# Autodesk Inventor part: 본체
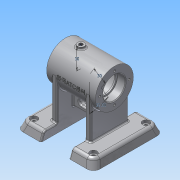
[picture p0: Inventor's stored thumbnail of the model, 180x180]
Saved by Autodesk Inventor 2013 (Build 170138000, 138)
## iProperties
Created: 2008-12
Part Number: 본체
Material: 알루미늄 6061
Document SubType Name: Modeling
Designer: Administrator
Density: 2.71 g/cm^3
Mass: 496.94 g
Surface Area: 538.478 cm^2
Volume: 183.373 cm^3
Author: Administrator
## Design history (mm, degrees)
sketch "스케치1"
  geometry: C1 r 27 at (0, 0); 1 further point
  constraints: 1 centre point, 1 coincident
  dimensions: "d0" = 54 diameter of C1
extrude "돌출1" new body sketch "스케치1" distance "d1" = 35; taper "d2" = 0 deg
sketch "스케치2"
  geometry: C1 r 27 at (0, 0) reference; C2 r 16 at (0, 0)
  constraints: 1 centre point, 1 coincident
  dimensions: "d3" = 32 diameter of C2
extrude "돌출2" cut sketch "스케치2" distance "d4" = 12; taper "d5" = 0 deg
sketch "스케치3"
  geometry: C1 r 16 at (0, 0) reference; C2 r 14 at (0, 0)
  constraints: 1 centre point, 1 coincident
  dimensions: "d6" = 28 diameter of C2
extrude "돌출3" cut sketch "스케치3" distance "d7" = 2; taper "d8" = 0 deg
sketch "스케치4"
  geometry: C1 r 14 at (0, 0) reference; C2 r 22 at (0, 0)
  constraints: 1 centre point, 1 coincident
  dimensions: "d9" = 44 diameter of C2
extrude "돌출4" cut sketch "스케치4" stored distance "d10" = 2; taper "d11" = 0 deg
chamfer "모따기1" distance "d12" = 1; stored, may be unused: second distance "d13" = 2, angle "d14" = 45 deg
fillet "모깎기1" dims "d15" = 0.3
sketch "스케치5"
  geometry: L1 (0, 0)-(0, 21); C1 r 17 at (0, 0) reference; 1 further point
  constraints: 2 end point, 1 coincident, 1 vertical
  dimensions: "d16" = 21 distance of L1.start L1.end
hole "구멍1" sketch "스케치5" at (0, 21) diameter "d17" = 3.242; stored, may be unused: countersink angle "d21" = 90 deg, drill point angle "d23" = 118 deg; dims "d18" = 8, "d19" = 4, "d20" = 2, "d22" = 10
node "작업 평면1"
node "작업 평면3"
sketch "스케치9"
  geometry: L1 (0, 0)-(-30, 0)
  constraints: 2 end point, 1 horizontal
  dimensions: "d44" = 30 distance of L1.start L1.end
node "작업 평면4"
sketch "스케치10"
  geometry: L1 (-22, -27)-(-22, 27) reference; L2 (48, -27)-(48, 27) reference; C1 r 5 at (0, 0); 4 further points
  constraints: 1 centre point, 1 coincident
  dimensions: "d45" = 10 diameter of C1
extrude "돌출6" join sketch "스케치10" stored distance "d46" = 2; taper "d47" = 0 deg
sketch "스케치11"
  geometry: C1 r 5 at (0, 0) reference; 2 further points
  constraints: 1 coincident
hole "구멍3" sketch "스케치11" at (0, 0) diameter "d48" = 5.188; stored, may be unused: countersink angle "d52" = 90 deg, drill point angle "d54" = 118 deg; dims "d49" = 99, "d50" = 4, "d51" = 2, "d53" = 10
fillet "모깎기4" dims "d55" = 2
node "작업 평면5"
sketch "스케치13"
  geometry: L1 (0, 0)-(9.92, 0); L2 (0, 0)-(25.441, 15.898)
  constraints: 4 end point, 1 horizontal
  dimensions: "d57" = 30 distance of L1.start L2.end; "d58" = 32 deg angle of L1 L2
node "작업 평면6"
sketch "스케치14"
  geometry: C1 r 6 at (0, 0); 1 further point
  constraints: 1 centre point, 1 coincident
  dimensions: "d59" = 12 diameter of C1
extrude "돌출7" join sketch "스케치14" stored distance "d60" = 2; taper "d61" = 0 deg
fillet "모깎기5" dims "d62" = 2
hole "구멍4" diameter "d65" = 5.188; stored, may be unused: countersink angle "d69" = 90 deg, drill point angle "d71" = 118 deg; dims "d63" = 10, "d64" = 10, "d66" = 99, "d67" = 4, "d68" = 2, "d70" = 10
node "작업 평면8"
  node "작업 평면7"
sketch "스케치16"
  geometry: L1 (-55, -50)-(55, -50); L2 (55, -50)-(55, 50); L3 (55, 50)-(-55, 50); L4 (-55, 50)-(-55, -50); L5 (-55, -50)-(55, 50); L6 (55, -50)-(-55, 50); 1 further point
  constraints: 12 end point, 2 midpoint, 2 parallel, 1 horizontal, 1 perpendicular
  dimensions: "d74" = 110 distance of L3.end L2.end; "d75" = 100 distance of L2.end L1.end
extrude "돌출8" join sketch "스케치16" distance "d76" = 12; taper "d77" = 0 deg
sketch "스케치17"
  geometry: L1 (0, 0)-(110, 0) reference; L2 (110, 0)-(110, 12) reference; L3 (0, 12)-(110, 12) reference; L4 (105.632, 12)-(110, 0); 1 further point
  constraints: 2 end point, 1 point on line
  dimensions: "d78" = 110 deg angle of L1 L4
extrude "돌출9" cut sketch "스케치17" stored distance "d79" = 12; taper "d80" = 0 deg
sketch "스케치18"
  geometry: L1 (0, 100)-(0, 0) reference; L2 (0, 0)-(12, 0) reference; L3 (12, 100)-(12, 0) reference; L4 (0, 0)-(12, 4.368); 1 further point
  constraints: 2 end point, 1 point on line
  dimensions: "d81" = 110 deg angle of L1 L4
extrude "돌출10" cut sketch "스케치18" stored distance "d82" = 12; taper "d83" = 0 deg
fillet "모깎기6" dims "d84" = 10
fillet "모깎기7" dims "d85" = 5
sketch "스케치19"
  geometry: L1 (-20, 4)-(20, 4); L2 (20, 4)-(20, -4); L3 (20, -4)-(-20, -4); L4 (-20, -4)-(-20, 4); L5 (-20, 4)-(20, -4); L6 (20, 4)-(-20, -4); L7 (20, -4)-(-20, -4); L8 (-20, -4)-(-20, -60.931); L9 (-20, -60.931)-(20, -60.931); L10 (20, -60.931)-(20, -4); L11 (20, 4)-(-20, 4); L12 (-20, 4)-(-20, 65.764); L13 (-20, 65.764)-(20, 65.764); L14 (20, 65.764)-(20, 4); 1 further point
  constraints: 28 end point, 6 parallel, 3 horizontal, 3 perpendicular, 2 midpoint
  dimensions: "d86" = 40 distance of L2.end L3.end; "d87" = 8 distance of L1.end L2.end
extrude "돌출11" cut sketch "스케치19" distance "d88" = 12; taper "d89" = 0 deg
sketch "스케치20"
  geometry: L1 (-20, -42.131)-(-20, 42.131) reference; L2 (-28, 27)-(-20, 27); L3 (-20, 27)-(-20, -27); L4 (-20, -27)-(-28, -27); L5 (-28, -27)-(-28, 27); 2 further points
  constraints: 8 end point, 2 midpoint, 2 parallel, 1 horizontal, 1 perpendicular
  dimensions: "d90" = 8 distance of L3.end L4.end; "d91" = 54 distance of L2.end L3.end
extrude "돌출12" join sketch "스케치20" stored distance "d92" = 12; taper "d93" = 0 deg
fillet "모깎기8" dims "d94" = 2
fillet "모깎기9" dims "d95" = 2
fillet "모깎기10" dims "d96" = 2
node "작업 평면10"
  node "작업 평면9"
sketch "스케치22"
  geometry: L1 (20, -47.872)-(20, 47.872) reference; L2 (-20, -4)-(20, -4); L3 (20, -4)-(20, 4); L4 (20, 4)-(-20, 4); L5 (-20, 4)-(-20, -4); L6 (-20, -4)-(20, 4); L7 (20, -4)-(-20, 4); 1 further point
  constraints: 12 end point, 2 midpoint, 2 parallel, 1 horizontal, 1 perpendicular, 1 point on line
  dimensions: "d113" = 8 distance of L3.end L2.end
extrude "돌출13" join sketch "스케치22" stored distance "d114" = 12; taper "d115" = 0 deg
sketch "스케치23"
  geometry: L1 (12, 13.5)-(28, 13.5); L2 (28, 6.5)-(12, 6.5); L3 (20, 6.5)-(20, 13.5); L4 (55, 21)-(55, 75) reference; L5 (42, -22)-(65.603, -22) reference; A1 r 3.5 centre (28, 10) between (28, 6.5) and (28, 13.5); A2 r 3.5 centre (12, 10) between (12, 13.5) and (12, 6.5); 1 further point
  constraints: 6 end point, 4 point on circle, 4 tangent, 2 centre point, 2 midpoint, 1 horizontal alignment
  dimensions: "d116" = 7 diameter of A1; "d117" = 7 diameter of A2; "d118" = 23 dimension on A1 A2; "d119" = 35 distance between parallel lines of L4 L3; "d120" = 11.5 dimension on A2 L3 (derived); "d121" = 32 distance from line of A1.centre L5
extrude "돌출14" cut sketch "스케치23" distance "d122" = 12; taper "d123" = 0 deg
fillet "모깎기11" dims "d124" = 2
fillet "모깎기12" dims "d125" = 2
fillet "모깎기13" dims "d126" = 2
sketch "스케치24"
  geometry: L1 (42.5, -37.5)-(-42.5, -37.5); L2 (-42.5, -37.5)-(-42.5, 37.5); L3 (-42.5, 37.5)-(42.5, 37.5); L4 (42.5, 37.5)-(42.5, -37.5); L5 (42.5, -37.5)-(-42.5, 37.5); L6 (-42.5, -37.5)-(42.5, 37.5); A1 r 5 centre (-42.5, 37.5) between (-47.131, 35.616) and (-40.616, 42.131) reference; 5 further points
  constraints: 12 end point, 4 coincident, 2 midpoint, 2 parallel, 1 horizontal, 1 perpendicular
  dimensions: "d127" = 85 distance of L2.end L3.end (derived); "d128" = 75 distance of L1.end L2.end (derived)
hole "구멍6" sketch "스케치24" at (-42.5, -37.5), (42.5, -37.5), (42.5, 37.5), (-42.5, 37.5) diameter "d129" = 6; stored, may be unused: countersink angle "d133" = 90 deg, drill point angle "d135" = 118 deg; dims "d130" = 99, "d131" = 10, "d132" = 4, "d134" = 10
fillet "모깎기14" dims "d136" = 2
node "작업 평면11"
sketch "스케치25"
  geometry: L1 (-35, -27)-(-35, 27) reference; L2 (-35, 27)-(35, 27) reference; 2 further points
  constraints: 1 other
  dimensions: "d137" = 35 distance from line of L1 point (0, 0); "d138" = 27 distance from line of L2 point (0, 0)
feature "엠보싱1" sketch "스케치25" dims "d139" = 0.5, "d140" = 0
fillet "모깎기15" dims "d141" = 3
node "솔리드1"
pattern_circular "원형 패턴1" dims angle "d25" = 360 deg
mirror "대칭1"
mirror "대칭2"
mirror "대칭3"
mirror "대칭4"
node "투영된 루프1"
other parameters: "d28" = -22, "d43" = -48, "d56" = -35, "d112" = -21
